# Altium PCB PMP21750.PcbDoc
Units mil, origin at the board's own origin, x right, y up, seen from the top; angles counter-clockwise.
Board outline 1000 x 600 mil, 2 copper layers (Top Layer, Bottom Layer), stack 62 mil thick; 15 components, 8 nets, 31 pads, 0 vias.
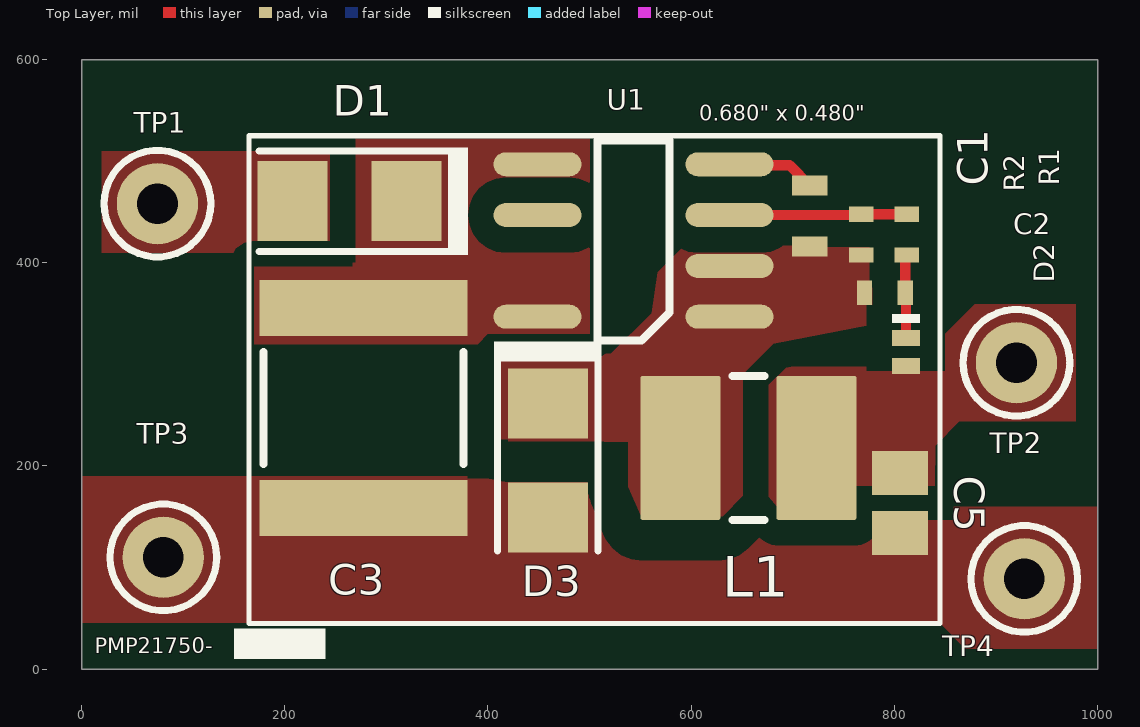
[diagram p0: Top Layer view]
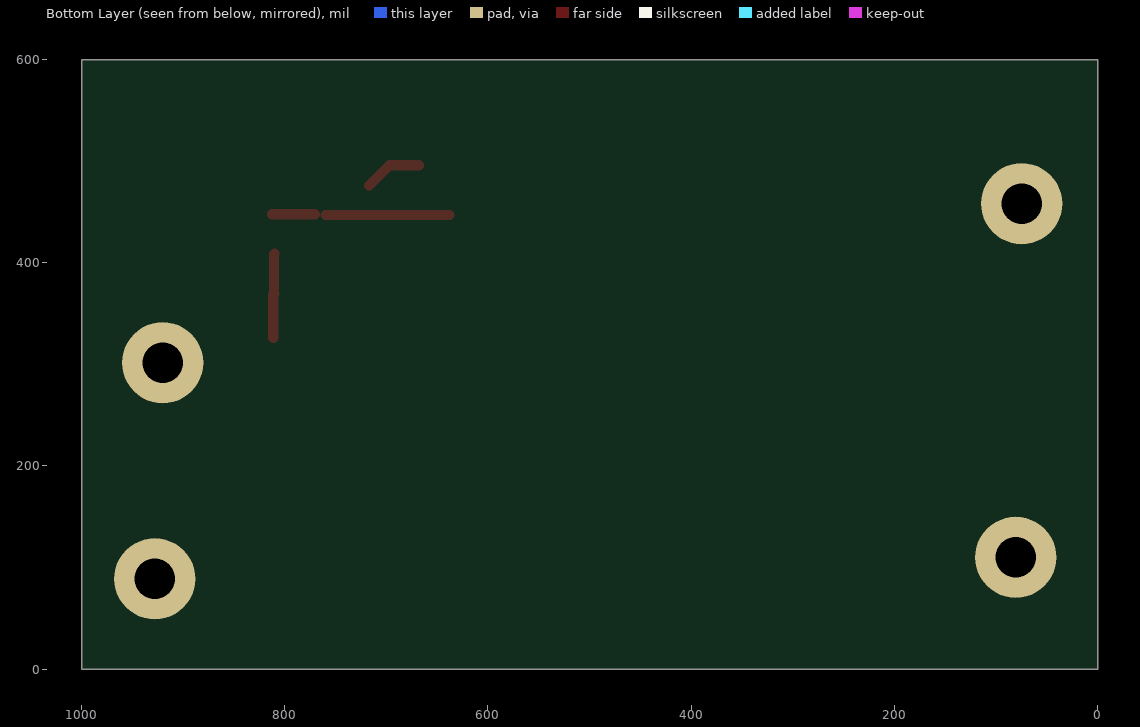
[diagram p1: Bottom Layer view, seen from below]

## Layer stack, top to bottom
Top Solder: solder mask 0.4, Solder Resist, Dk 3.5
Top Layer: signal copper 1.4
Dielectric1: core 59.2, FR-4, Dk 4.8
Bottom Layer: signal copper 1.4
Bottom Solder: solder mask 0.4, Solder Resist, Dk 3.5

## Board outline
0,0 0,600 1000,600 1000,0

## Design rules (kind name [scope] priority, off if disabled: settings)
AcuteAngle [All] p1: minimum=4.50000000000000E+0001 checktracksonly=FALSE
AssemblyTestPointUsage [All] p1: valid=2
Clearance Clearance_1 [InNetClass('HV') vs InNet('GND')] p1: gap=40 ignorepadtopadclearanceinfootprint=FALSE
Clearance Clearance_BoardEdge_MountingHoles [OnCopper and InComponentClass('Mounting Holes') vs IsKeepOut] p2: gap=40 ignorepadtopadclearanceinfootprint=FALSE except(0: Arc-Hole Track-Hole SMDPad-Hole THPad-Hole Via-Hole Fill-Hole Poly-Hole Region-Hole Text-Hole)
Clearance Clearance_BoardEdge_Poly [OnCopper and InPoly vs IsKeepOut] p3: gap=25 ignorepadtopadclearanceinfootprint=FALSE except(0: Arc-Hole Track-Hole SMDPad-Hole THPad-Hole Via-Hole Fill-Hole Poly-Hole Region-Hole Text-Hole)
Clearance Clearance_BoardEdge [OnCopper and Not InComponentClass('Logo') and not InComponentClass('FiducialMark') and not InRegion(1000,500,4000,800) and Not IsKeepout vs IsKeepOut] p4: gap=75 ignorepadtopadclearanceinfootprint=FALSE except(0: Arc-Hole Track-Hole SMDPad-Hole THPad-Hole Via-Hole Fill-Hole Poly-Hole Region-Hole Text-Hole)
Clearance Clearance_Poly [InPolygon] p5: gap=25 ignorepadtopadclearanceinfootprint=FALSE except(0: Arc-Hole Track-Hole SMDPad-Hole THPad-Hole Via-Hole Fill-Hole Poly-Hole Region-Hole Text-Hole)
Clearance [All] p6: gap=8 ignorepadtopadclearanceinfootprint=FALSE except(0: Arc-Hole Track-Hole SMDPad-Hole THPad-Hole Via-Hole Fill-Hole Poly-Hole Region-Hole Text-Hole)
ComponentClearance ComponentClearance_ScrewToNut [(HasFootprint('NY PMS 440 0025 PH')) vs (HasFootprint('Keystone_1902C'))] p1: gap=5 collisioncheckmode=3 verticalgap=10 showdistances=FALSE
ComponentClearance ComponentClearance_MountingHoles [InComponentClass('Mounting Holes')] p2: gap=2 collisioncheckmode=3 verticalgap=100000 showdistances=FALSE
ComponentClearance ComponentClearance_SmallPassives [HasFootprint('0201*') or HasFootprint('0402*') or HasFootprint('0508') or HasFootprint('0603*') or HasFootprint('0612') or HasFootprint('0805*') or HasFootprint('0815*') or HasFootprint('0830*') or HasFootprint('1206*') or HasFootprint('1210*') or HasFootprint('1808*') or HasFootprint('1812*') or HasFootprint('1825*') or HasFootprint('2010*') or HasFootprint('2220*') or HasFootprint('2225*') or HasFootprint('2512*') or HasFootprint('2728*') or HasFootprint('3518*') vs HasFootprint('0201*') or HasFootprint('0402*') or HasFootprint('0508') or HasFootprint('0603*') or HasFootprint('0612') or HasFootprint('0805*') or HasFootprint('0815*') or HasFootprint('0830*') or HasFootprint('1206*') or HasFootprint('1210*') or HasFootprint('1808*') or HasFootprint('1812*') or HasFootprint('1825*') or HasFootprint('2010*') or HasFootprint('2220*') or HasFootprint('2225*') or HasFootprint('2512*') or HasFootprint('2728*') or HasFootprint('3518*')] p3: gap=20 collisioncheckmode=3 verticalgap=10 showdistances=FALSE
ComponentClearance ComponentClearance_THtoSMT [IsThruComponent vs IsSMTComponent] p4: gap=20 collisioncheckmode=3 verticalgap=10 showdistances=FALSE
ComponentClearance ComponentClearance_THtoTH [IsThruComponent vs IsThruComponent] p5: gap=20 collisioncheckmode=3 verticalgap=20 showdistances=FALSE
ComponentClearance [All] p6: gap=10 collisioncheckmode=3 verticalgap=10 showdistances=FALSE
DiffPairsRouting [All] p1: maxlimit=100 minlimit=10 mostfreqgap=10 toplayer_minwidth=15 toplayer_maxwidth=15 toplayer_prefwidth=15 bottomlayer_minwidth=15 bottomlayer_maxwidth=15 bottomlayer_prefwidth=15 maxuncoupledlength=1000
FabricationTestPointUsage TestPointUsage [All] p1: valid=2 allowmultiple=FALSE
FabricationTestpoint Testpoint [All] p1: side=3 testpointundercomponent=TRUE minsize=40 maxsize=100 preferedsize=60 minholesize=0 maxholesize=40 preferedholesize=32 testpointgrid=1 allowsidetop=TRUE allowsidebottom=TRUE usegrid=TRUE gridtolerance=0.01
FanoutControl Fanout_LCC [IsLCC] p1: bgadir=Out bgaviamode=Centered fanoutstyle=Auto fanoutdirection=Alternating viagrid=1 // Fanout_LCC (Default Rule)
FanoutControl Fanout_BGA [IsBGA] p2: bgadir=Out bgaviamode=Centered fanoutstyle=Auto fanoutdirection=Alternating viagrid=1 // Fanout_BGA (Default Rule)
FanoutControl Fanout_Default [All] p4: bgadir=Out bgaviamode=Centered fanoutstyle=Auto fanoutdirection=Alternating viagrid=1 // Fanout_Default (Default Rule)
FanoutControl Fanout_Small [(CompPinCount < 5)] p5: bgadir=Out bgaviamode=Centered fanoutstyle=Auto fanoutdirection=OutThenIn viagrid=1 // Fanout_Small (Default Rule)
HoleSize [All] p1: absolutevalues=TRUE maxlimit=251 minlimit=8 maxpercent=80.000 minpercent=20.000
MinimumAnnularRing [All] p1: minimumring=9
MinimumSolderMaskSliver MinimumSolderMaskSliver_Logo [InComponentClass('Logo') vs InComponentClass('Logo')] p1: minsoldermaskwidth=0.7
MinimumSolderMaskSliver [All] p2: minsoldermaskwidth=4
PlaneConnect [All] p1: planeconnectstyle=Relief reliefexpansion=10 reliefentries=4 reliefconductorwidth=10 reliefairgap=10
PolygonConnect [All] p1: connectstyle=Direct reliefconductorwidth=20 reliefentries=4 polygonreliefangle="90 Angle" airgapwidth=10
RoutingVias [All] p1: holewidth=16 width=34 viastyle="Through Hole" minholewidth=8 minwidth=26 maxholewidth=40 maxwidth=65
SMDToCorner [All] p1: distance=30000
SilkToSilkClearance [All] p1: silktosilkclearance=5
SilkToSolderMaskClearance SilkscreenOverComponentPads [IsPad] p1: minsilkscreentomaskgap=5 clearancetoexposedcopper=TRUE
SolderMaskExpansion [All] p1: expansion=3
Width [All] p1: maxlimit=100 minlimit=6 preferedwidth=10 checkconnectedcopper=TRUE
16 further rules are at their usual default settings.

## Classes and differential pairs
net class HV: NetC1_2 NetC3_1

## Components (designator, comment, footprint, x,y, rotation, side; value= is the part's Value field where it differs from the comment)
C1 "C0603C104K8RACTU" 0603S 716.79,446.02 r270 top value=0.1uF
C2 "GRM155R71A224KE01D" 0402S 790.67,370.48 r180 top value=0.22uF
C3 "Capacitor" 2220_280L 277.63,257.08 r270 top value=2.2uF
C5 "GRM21BR60J107M" 0805L 805.8,163.45 r270 top value=100uF
D1 "CD1408-FU1600" Diode_1408 263.49,460.67 r180 top value=600V
D2 "BAS16L,315" SOD882 811.33,312.12 r270 top value=100V
D3 "CD1408-FU1600" Diode_1408 458.94,205.58 r270 top value=600V
L1 "744045681" WE-LQ_1812 656.41,217.8 r0 top value=680uH
R1 "CRCW040243K2FKED" 0402S 812.26,427.76 r270 top value=43.2k
R2 "ERJ-2RKF1002X" 0402S 767.43,427.76 r90 top value=10.0k
TP1 "5000" Keystone5000 74.72,458.19 r90 top
TP2 "5000" Keystone5000 920.18,301.57 r90 top
TP3 "5001" Keystone5001 80.53,110.04 r90 top
TP4 "5001" Keystone5001 927.9,88.88 r90 top
U1 "UCC28880D" D0007A_N 543.36,421.92 r180 top

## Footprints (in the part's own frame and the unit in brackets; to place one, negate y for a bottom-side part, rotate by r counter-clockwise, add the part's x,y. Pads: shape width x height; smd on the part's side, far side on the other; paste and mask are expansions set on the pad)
0402S [mil] "Based on C0402S footprint from PADS legacy"
  rect 15x24 smd: 1(-20,0) 2(20,0)
  body extent -22,-12 22,12, height 24
0603S [mil]
  rect 20x35 smd: 1(-30,0) 2(30,0)
  body extent -34,-19 34,19, height 39
0805L [mm] "0805 from SM-752 data"
  rect 1.1x1.4 smd: 1(-0.75,0) 2(0.75,0)
  body extent -1.1,-0.72 1.1,0.72, height 1.45
2220_280L [mm] "Chip Capacitor, Body 5.7x5.0mm, IPC High Density"
  rect 1.4x5.2 smd: 1(-2.5,0) 2(2.5,0)
  silkscreen extent -1.4,-2.5 1.4,2.5, body extent -2.95,-2.6 2.95,2.65, height 2.8
D0007A_N [mm] "SOIC, 7-Leads, Body 4.9x3.9mm, Pitch 1.27mm, IPC Medium Density"
  oval 2.2x0.6 smd: 1(-2.4,1.905) 2(-2.4,0.635) 3(-2.4,-0.635) 4(-2.4,-1.905) 5(2.4,-1.905) 6(2.4,-0.635) 8(2.4,1.905)
  silkscreen extent -0.9,-2.5 0.9,2.5, body extent -3,-2.5 3,2.5, height 1.54
Diode_1408 [mm] "On Semi recommended land pattern for SOD-123"
  rect 1.75x2 smd: 1(-1.425,0) 2(1.425,0)
  silkscreen extent -2.97,-1.35 2.26,1.35, body extent -1.8,-1.05 1.8,1.05, height 1.35
Keystone5000 [mil] "For Keystone 500x miniature loop terminals"
  round 80 hole 40: 1(0,0)
  silkscreen extent -52,-52 52,52, body extent -49,-49 49,49, height 182
Keystone5001 [mil] "For Keystone 500x miniature loop terminals"
  round 80 hole 40: 1(0,0)
  silkscreen extent -52,-52 52,52, body extent -49,-49 49,49, height 182
SOD882 [mm] "NXP Semiconductor"
  rect 0.4x0.7 smd paste-0.05: 1(-0.35,0) 2(0.35,0)
  silkscreen extent -0.95,-0.35 -0.72,0.35, body extent -0.51,-0.31 0.51,0.31, height 0.51
WE-LQ_1812 [mm] "SMD, 2-Leads, Body 4.5x3.2mm"
  rrect5% 2x3.6 smd: 1(-1.7,0) 2(1.7,0)
  silkscreen extent -0.4,-1.8 0.4,1.8, body extent -2.25,-1.6 2.25,1.6, height 2.6

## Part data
C1: library part CMP-0006862-5, "CAP, CERM, 0.1 uF, 10 V, +/- 10%, X7R, 0603", Cap_Case=0603, Manufacturer=Kemet, Supplier Part Number 1=399-1095-1-ND, TempCo=X7R, Tolerance_%=10%, Value1=Unknown, Value2=10V, ValueDisplayed=0.1uF
C2: library part CMP-0006630-2, "CAP, CERM, 0.22 uF, 10 V, +/- 10%, X7R, 0402", Cap_Case=0402, Manufacturer=MuRata, Supplier Part Number 1=490-12706-1-ND, TempCo=X7R, Tolerance_%=10%, Value1=Unknown, Value2=10V, ValueDisplayed=0.22uF
C3: library part CMP-0009372-2, "CAP, CERM, 2.2 uF, 450 V, +/- 10%, X6S, 2220", Cap_Case=2220, Manufacturer=TDK, PartNumber=C5750X6S2W225K250KA, Supplier Part Number 1=445-7781-1-ND, TempCo=X6S, Tolerance_%=10%, Value1=Unknown, Value2=450V, ValueDisplayed=2.2uF
C5: library part CMP-0008280-2, "CAP, CERM, 100 uF, 6.3 V, +/- 20%, X5R, 0805", Cap_Case=0805, Manufacturer=MuRata, TempCo=X5R, Tolerance_%=20%, Value1=Unknown, Value2=6.3V, ValueDisplayed=100uF
D1 D3: library part CMP-0029015-1, "Diode, Ultrafast, 600 V, 1 A, 1408 Diode", Manufacturer=Bourns, Supplier Part Number 1=CD1408-FU1600CT-ND, Value1=1A, Value2=1.25V
D2: library part CMP-0076954-1, "Diode, Switching, 100 V, 0.215 A, SOD882", Manufacturer=Nexperia, Supplier Part Number 1=568-4859-1-ND, Value1=0.215A, Value2=1.25V
L1: library part CMP-0084743-1, "Inductor, Wirewound, Ferrite, 680 µH, 0.09 A, 16.8 ohm, SMD", Manufacturer="Wurth Elektronik", Value1="16.8 ohm", Value2=0.09A, ValueDisplayed=680µH
R1: library part CMP-0026379-2, "RES, 43.2 k, 1%, 0.063 W, AEC-Q200 Grade 0, 0402", Manufacturer=Vishay-Dale, Power_W=63mW, Supplier Part Number 1=541-43.2KLCT-ND, TempCo="100 ppm/C", Tolerance_%=1%, Value2=0.063W, Value_Code=43k2, ValueDisplayed=43.2k
R2: library part CMP-0026658-1, "RES, 10.0 k, 1%, 0.1 W, 0402", Manufacturer=Panasonic, Power_W=100mW, Supplier Part Number 1=P10.0KLCT-ND, TempCo="100 ppm/C", Tolerance_%=1%, Value2=0.1W, Value_Code=10k0, ValueDisplayed=10.0k
TP1 TP2: library part CMP-0055137-1, "Test Point, Miniature, Red, TH", Color=Red, Manufacturer=Keystone, Supplier Part Number 1=36-5000-ND
TP3 TP4: library part CMP-0055138-1, "Test Point, Miniature, Black, TH", Color=Black, Manufacturer=Keystone, Supplier Part Number 1=36-5001-ND
U1: "Low Quiescent Current Switcher IC for AC/DC Power Supplies, D0007A", Alternate Manufacturer=None, Manufacturer="Texas Instruments"

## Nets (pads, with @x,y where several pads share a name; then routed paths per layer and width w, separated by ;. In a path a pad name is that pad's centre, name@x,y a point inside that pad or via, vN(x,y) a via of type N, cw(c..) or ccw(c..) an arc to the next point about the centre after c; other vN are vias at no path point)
GND: C3.2 C5.2 D3.2 TP3.1 TP4.1
NetC1_1: C1.1 U1.4 | length 56.9
  Top Layer w10: U1.4@668.12,495.9 696.91,495.9 C1.1
NetC1_2: C1.2 C2.2 D3.1 L1.1 R2.1 U1.1 U1.2
NetC2_1: C2.1 D2.1 R1.2 | length 83
  Top Layer w10: C2.1@810.17,369.8 811.33,368.64 D2.1 ; R1.2@810.17,408.91 810.67,408.41 C2.1
NetC3_1: C3.1 D1.1 U1.5 U1.8
NetC5_1: C5.1 D2.2 L1.2 TP2.1
NetD1_2: D1.2 TP1.1
NetR1_1: R1.1 R2.2 U1.3 | length 164.1
  Top Layer w10: U1.3 759.91,446.92 R2.2@759.98,446.85 ; R2.2@770.36,447.81 770.41,447.76 R1.1
pads on no net: U1.6

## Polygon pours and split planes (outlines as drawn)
GND on Top Layer "GND_L01_P054" (solid, remove dead copper, pour order 54): 0,190 840,190 840,160 1000,160 1000,20 870,20 844.45,45.55 0,45.55
NetC5_1 on Top Layer "NETC5_1_L01_P050" (solid, remove dead copper, pour order 50): 670,297.88 670,159.61 840,159.61 840,220 864.02,244.02 978.68,244.02 978.68,359.34 879.34,359.34 817.88,297.88
NetC1_2 on Top Layer "NETC1_2_L01_P048" (solid, remove dead copper, pour order 48): 411.01,310.45 411.01,224.38 514.09,224.38 522.1,216.38 551.01,150.45 631.01,150.45 651.01,170.45 651.01,290.45 681.01,320.45 779,339.19 785.18,421.82 598.17,421.82 567.01,390.66 561.01,350.45 521.01,310.45
NetD1_2 on Top Layer "NETD1_2_L01_P046" (solid, remove dead copper, pour order 46): 250,510 20,510 20,410 250,410
NetC3_1 on Top Layer "NETC3_1_L01_P044" (solid, pour order 44): 500,522.24 270,522.24 270,400 170,400 170,320 390,320 400,330 500,330
no net on Top Layer "NONET_L01_P026" (solid, remove dead copper, pour order 26): 0,190
no net on Top Layer "NONET_L01_P022" (solid, remove dead copper, pour order 22): 223.59,518.64
no net on Top Layer "NONET_L01_P018" (solid, remove dead copper, pour order 18): 25.32,512.9
no net on Top Layer "NONET_L01_P016" (solid, remove dead copper, pour order 16): 1005.17,429.57
no net on Top Layer "NONET_L01_P012" (solid, remove dead copper, pour order 12): 615.1,-237.08
no net on Top Layer "NONET_L01_P010" (solid, remove dead copper, pour order 10): -382.73,4086.55
no net on Top Layer "NONET_L01_P002" (solid, remove dead copper, pour order 2): 348.19,388.74

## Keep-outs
Keep-Out Layer:
  text ".Layer_Name" at 397,-978.49 h60

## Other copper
Top Layer:
  text ".Layer_Name" at 397,-978.49 h60
Bottom Layer:
  text ".Layer_Name" at 397,-978.49 h60

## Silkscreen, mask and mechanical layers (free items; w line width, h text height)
Top Overlay:
  rectangle: 150,10 240,40
  lines w5: 165,45 165,525 845,525 845,45 165,45
  text "0.680\" x 0.480\"" at 607.97,539.69 h15
  text "PMP21750-" at 13.05,15.85 h15
  text ".Layer_Name" at 397,-978.49 h60
Bottom Overlay:
  text ".Layer_Name" at 397,-978.49 h60
Top Paste:
  text ".Layer_Name" at 397,-978.49 h60
Bottom Paste:
  text ".Layer_Name" at 397,-978.49 h60
Top Solder:
  text ".Layer_Name" at 397,-978.49 h60
  text ".Layer_Name" at 397,-978.49 h60
Bottom Solder:
  text ".Layer_Name" at 397,-978.49 h60
Drill Guide:
  text ".Layer_Name" at 397,-978.49 h60
M1 Board Outline:
  the board outline again, w10
  text ".Layer_Name" at 397,-978.49 h60
M2 Board Dimensions:
  rectangle: -180.5,-405.5 -55.5,-280.5
  rectangle: -55.5,-530.5 319.5,-405.5
  lines w7: -180.5,-405.5 819.5,-405.5 ; -55.5,-530.5 -55.5,-280.5 ; 69.5,-530.5 69.5,-280.5 ; 319.5,-530.5 319.5,-280.5 ; 569.5,-530.5 569.5,-280.5 ; -180.5,-530.5 819.5,-530.5 819.5,-280.5 -180.5,-280.5 -180.5,-530.5
  lines w10: -180.5,-595.5 -180.5,-575.5 ; -120.5,-605.5 -180.5,-585.5 ; -120.5,-565.5 -180.5,-585.5 ; 43.58,-585.5 -180.5,-585.5 ; 595.42,-585.5 819.5,-585.5 ; 759.5,-605.5 819.5,-585.5 ; 759.5,-565.5 819.5,-585.5 ; 819.5,-595.5 819.5,-575.5
  text "1000 (mil)" at 53.58,-621.49 h60
  text ".Layer_Name" at 397,-978.49 h60
M3 3D STEP Top:
  text ".Layer_Name" at 397,-978.49 h60
M4 3D STEP Bottom:
  text ".Layer_Name" at 397,-978.49 h60
M5 Assembly Top:
  lines w7: 4959,-9.5 6084,-9.5 ; 4959,113 6081.5,113 ; 5274,-129.5 5274,233 ; 5659,-129.5 4959,-129.5 ; 5659,233 4959,233 ; 4959,-129.5 6084,-129.5 6084,233 4959,233 ; 4959,-129.5 4959,233
  lines w10: -472,-1050.17 6128,-1050.17 ; -472,-846.83 6130,-846.83 ; -472,-643.5 -472,-1253.5 3533,-1253.5 6130,-1253.5 6130,-643.5 -471.5,-643.5 -471.5,-1253.5 1104,-1253.5 ; 1993,-1253.5 1993,-643.5 ; 3260,-846.83 3260,-643.5 ; 4100,-846.83 4100,-643.5 ; 4722,-1260 4722,-1057.17
  text "TABLE 1" at 5346.5,268 h40
  text "Variant" at 4984,158 h40
  text "Label text" at 5419,158 h40
  text "001" at 5051.5,38 h40
  text "ChangeMe!" at 5329,35.5 h40
  text "002" at 5051.5,-87 h40
  text "ChangeMe!" at 5324,-89.5 h40
  text "COMPONENTS MARKED 'DNP' SHOULD NOT BE POPULATED." at 973.5,-438.5 h60
  text "ASSEMBLY VARIANT:" at 973,-554 h60
  text ".VariantName" at 2009,-554 h60
  text "PCB VIEWED FROM TOP SIDE" at -408.5,-775.67 h60
  text "BOARD #:" at 2068,-775.67 h60
  text ".PRJ_Number" at 2613.5,-775.67 h60
  text "REV:" at 3458,-775.67 h60
  text ".PCB_Rev" at 3749.5,-775.67 h60
  text "SVN REV:" at 4296,-775.67 h60
  text ".VersionControl_RevNumber" at 4802,-775.67 h60
  text "IGNORE ->" at -408.5,-978.49 h60
  text "PLOT NAME =" at -408.5,-1184.34 h60
  text ".plot_File_Name" at 397,-1184.34 h60
  text "GENERATED    :" at 2070,-1184.34 h60
  text ".Print_Date" at 2939.5,-1184.34 h60
  text ".Print_Time" at 3668.5,-1184.34 h60
  text "TEXAS INSTRUMENTS" at 4933,-1184.34 h60
M6 Assembly Bottom:
  lines w10: -472.5,-847.33 6129.5,-847.33 ; -470.5,-1050.67 6129.5,-1050.67 ; 935.5,-1260.5 935.5,-1057.67 ; 1557.5,-847.33 1557.5,-644 ; 2397.5,-847.33 2397.5,-644 ; 3664.5,-1254 3664.5,-644 ; 4553.5,-1254 6129,-1254 6129,-644 -472.5,-644 -472.5,-1254 2124.5,-1254 6129.5,-1254 6129.5,-644
  text "COMPONENTS MARKED 'DNP' SHOULD NOT BE POPULATED." at 5922,-438 h60
  text ".VariantName" at 4878,-554 h60
  text "ASSEMBLY VARIANT:" at 5917,-554 h60
  text ".VersionControl_RevNumber" at 855.5,-776.17 h60
  text "SVN REV:" at 1361.5,-776.17 h60
  text ".PCB_Rev" at 1908,-776.17 h60
  text "REV:" at 2199.5,-776.17 h60
  text ".PRJ_Number" at 3044,-776.17 h60
  text "BOARD #:" at 3589.5,-776.17 h60
  text "PCB VIEWED FROM BOTTOM SIDE" at 6066,-776.17 h60
  text "IGNORE ->" at 2367.85,-978.49 h60
  text "TEXAS INSTRUMENTS" at 724.5,-1184.84 h60
  text ".Print_Time" at 1989,-1184.84 h60
  text ".Print_Date" at 2718,-1184.84 h60
  text "GENERATED    :" at 3587.5,-1184.84 h60
  text ".plot_File_Name" at 5260.5,-1184.84 h60
  text "PLOT NAME =" at 6066,-1184.84 h60
M9 Title Sheet:
  drawing of 57 lines, arcs and shapes, not listed
  text "1" at 559.84,7916.5 h70
  text "2" at 3055.5,7916.5 h70
  text "3" at 5544.84,7916.5 h70
  text "4" at 8051.51,7916.5 h70
  text "5" at 10550.5,7916.5 h70
  text "6" at 13055.5,7916.5 h70
  text "A" at -596.5,6773.5 h70
  text "A" at 14203.5,6773.5 h70
  text "B" at -596.5,4393.5 h70
  text "B" at 14203.5,4393.5 h70
  text "C" at -596.5,2018.5 h70
  text "C" at 14203.5,2018.5 h70
  text "PROJECT TITLE:" at 11163.5,157.5 h45
  text ".PRJ_Title" at 11213.5,24.17 h70
  text "DESIGNED FOR:" at 11163.5,-143.5 h45
  text ".PRJ_Customer" at 11213.5,-283.5 h70
  text "D" at -596.5,-351.5 h70
  text "D" at 14203.5,-351.5 h70
  text "FILE NAME:" at 11163.5,-443.5 h45
  text ".PCB_File_Name_No_Path" at 11213.5,-563.5 h70
  text "Texas Instruments (TI) and/or its licensors do not warrant the accuracy or completeness of this specification" at 6194,-725.34 h45
  text "ENGINEER:" at 11163.5,-733.5 h45
  text "LAYOUT BY:" at 12668.5,-733.5 h45
  text "or any information contained therein. TI and/or its licensors do not warrant that this design will meet" at 6149.01,-838 h45
  text ".PRJ_Engineer" at 11213.5,-888.49 h70
  text ".PCB_Layout" at 12719,-888.49 h70
  text "the specifications, will be suitable for your application or fit for any particular purpose, or will operate in" at 6149.01,-950.67 h45
  text ".Layer_Name" at 397,-978.49 h60
  text "ALTIUM DESIGNER VERSION:" at 12668.5,-1043.5 h45
  text "an implementation. TI and/or its licensors do not warrant that the design is production worthy. You should" at 6149.01,-1063.33 h45
  text "completely validate and test your design implementation to confirm the system functionality for your application." at 6194,-1176 h45
  text ".print_Scale" at 11213.5,-1176.83 h70
  text ".Application_BuildNumber" at 12719,-1176.83 h70
  text "1" at 559.84,-1383.5 h70
  text "2" at 3055.5,-1383.5 h70
  text "3" at 5544.84,-1383.5 h70
  text "4" at 8051.51,-1383.5 h70
  text "5" at 10550.5,-1383.5 h70
  text "6" at 13055.5,-1383.5 h70
M10 Fab Notes:
  drawing of 212 lines, arcs and shapes, not listed
  text "DESIGN INFORMATION" at 12201.02,6690 h60
  text "(REFER ALSO ARRAY/PANEL PROFILING INFORMATION)" at 11839.46,6528.29 h60
  text "BOARD SIZE" at 11153.46,6524 h60
  text "1500MIL" at 11615.78,6396.18 h60
  text "X" at 12121.46,6396.18 h60
  text "2100MIL" at 12352.78,6396.18 h60
  text "Number of Layers :" at 11556.46,6199 h60
  text "1" at 12651.27,6189 h60
  text "MIN. TRACK WIDTH:" at 11556.46,6060 h60
  text "10" at 12652.7,6060 h60
  text "MIL" at 12807.46,6060 h60
  text "MIN. CLEARANCE:" at 11556.46,5928 h60
  text "10" at 12652.7,5928 h60
  text "MIL" at 12807.46,5928 h60
  text "MIN. VIA PAD SIZE:" at 11556.46,5796 h60
  text "10" at 12622.71,5796 h60
  text "MIL" at 12807.46,5796 h60
  text "0.05mm (2MIL)" at 12251.46,5654.29 h60
  text "MINIMUM ANNULAR RING" at 11227.23,5650 h60
  text "EXTERNAL" at 12959.46,5650 h60
  text "PER" at 11427.23,5532 h60
  text "IPC-D-275 CLASS 2 LEVEL C" at 11647.23,5532 h60
  text "MIL, HOLES" at 13135.46,5419.71 h60
  text "+/-" at 12743,5419 h60
  text "+/-" at 13597,5419 h60
  text "REGISTRATION TOLERANCES:" at 11227.23,5414 h60
  text "METAL" at 12427,5414 h60
  text "5" at 13003.2,5414 h60
  text "3" at 13836.2,5414 h60
  text "MIL" at 13952.46,5414 h60
  text "MATERIAL:" at 11152.46,5204.54 h60
  text "FR-4 High Tg" at 12138.9,5064.21 h60
  text "FR-408" at 11573.46,5055.64 h60
  text "X" at 11985.46,5055.64 h60
  text "OTHER" at 13061.46,5055.64 h60
  text "62 MIL (1.6mm) +/-10%" at 11893.56,4892.92 h60
  text "THICKNESS:" at 11227.23,4888.64 h60
  text "X" at 11765.4,4888.64 h60
  text "OTHER" at 13178.46,4888.64 h60
  text "TOLERANCE:" at 11227.23,4730.64 h60
  text "X" at 12066.53,4730.64 h60
  text "ANSI IPC-6012 TYPE 3 CLASS 2" at 12253.48,4730.64 h60
  text "OTHER +/-" at 12253.46,4574.64 h60
  text "BOW & TWIST:" at 11227.23,4417.64 h60
  text "X" at 12066.53,4417.64 h60
  text "ANSI IPC-6012 TYPE 3 CLASS 2" at 12253.48,4417.64 h60
  text "OTHER +/-" at 12253.46,4259.13 h60
  text "COPPER THICKNESS (FINISHED):" at 11152.46,4123.64 h60
  text "1.4MIL (1oz)" at 12032.46,3970.92 h60
  text "2MIL (1.4oz)" at 12799.46,3970.92 h60
  text "2.8MIL (2oz)" at 13526.46,3970.92 h60
  text "OUTER:" at 11509.46,3966.64 h60
  text "X" at 11904,3966 h60
  text "X" at 13400,3820 h60
  text "1.4MIL (1oz)" at 12032.46,3813.92 h60
  text "2.8MIL (2oz)" at 12799.46,3813.92 h60
  text "N/A" at 13526,3814.29 h60
  text "INNER SIGNAL:" at 11220.38,3809.64 h60
  text "DRILLING:" at 11152.46,3670.64 h60
  text "REFERENCE:" at 11227.23,3553.64 h60
  text "X" at 11875.46,3553.64 h60
  text "AS SHOWN" at 12062.46,3553.64 h60
  text "X" at 12776.46,3553.64 h60
  text "NC_DRILL FILES" at 12913.46,3553.64 h60
  text "PTH MIN COPPER THICKNESS:" at 11227.23,3395.64 h60
  text "X" at 12577.46,3395.64 h60
  text "1MIL" at 12714.46,3395.64 h60
  text "OTHER" at 13211.46,3395.64 h60
  text "BOARD FINISH:" at 11152.46,3236.64 h60
  text "SILKSCREEN:" at 11307.68,3118.64 h60
  text "X" at 12256.46,3118.64 h60
  text "TOP" at 12382.46,3118.64 h60
  text "BOTTOM" at 12893.46,3118.64 h60
  text "SILKSCREEN COLOR:" at 11307.68,2951.64 h60
  text "X" at 12255.42,2951.64 h60
  text "WHITE" at 12382.46,2951.64 h60
  text "OTHER" at 12893.46,2951.64 h60
  text "SOLDER RESIST COLOR:" at 11307.68,2781.64 h60
  text "X" at 11875.42,2622.44 h60
  text "GREEN" at 12002.46,2622.44 h60
  text "BLUE" at 12593.46,2622.44 h60
  text "OTHER" at 13131.46,2622.44 h60
  text "IMMERSION GOLD (ENIG)" at 12213.46,2433.92 h60
  text "ENEPIG" at 13551,2430.64 h60
  text "SURFACE FINISH:" at 11152.46,2429.64 h60
  text "IMM. TIN/SILVER OR EQUIV" at 11482,2272.64 h60
  text "OTHER" at 12913.46,2272.64 h60
  text "X" at 11310,2270 h60
  text "ARRAY/PANEL:" at 11152.46,2093.64 h60
  text "CUT AND TRIM PER MECH LAYER 1" at 12213.46,2089.35 h60
  text "N.C. ROUTE" at 12213.46,1937.64 h60
  text "X" at 12892.46,1937.64 h60
  text "V. SCORE" at 13079.46,1937.64 h60
  text "CERTIFICATION:" at 11152.46,1800.64 h60
  text "MATERIALS AND WORKMANSHIP FOR ALL PCBS" at 11877.46,1800.64 h60
  text "TO MEET OR EXCEED THE REQUIREMENTS OF:" at 11877.46,1702.64 h60
  text "X" at 11503.96,1566.13 h60
  text "ANSI IPC-A-600F CLASS ->" at 11642.96,1566.13 h60
  text "X" at 13282.02,1566.13 h60
  text "2" at 13400.96,1566.14 h60
  text "1" at 13085.96,1564.64 h60
  text "3" at 13754.96,1564.64 h60
  text "X" at 11506.02,1406.64 h60
  text "UL 94V-0" at 11642.96,1406.64 h60
  text "X" at 12318.02,1406.64 h60
  text "RoHS" at 12454.96,1406.64 h60
  text "OTHER" at 13099.36,1406.64 h60
  text "PER ORDER" at 13496.42,1406.64 h60
  text "ADDITIONAL REQUIREMENTS:" at 11152.46,1265.64 h60
  text "MICROSECTION:" at 11227.23,1150.64 h60
  text "YES" at 12132.96,1150.64 h60
  text "REQUIRED" at 12994.46,994.49 h60
  text "BARE BOARD ELEC. TEST:" at 11227.23,991.64 h60
  text "NONE" at 12532.96,991.64 h60
  text "PER ORDER" at 13586.46,991.64 h60
  text "X" at 12410,990 h60
  text "MANUFACTURER'S UL:" at 11227.23,834.64 h60
  text "RAIL" at 12392.96,830.35 h60
  text "METAL" at 12884.77,830.35 h60
  text "X" at 13260,830 h60
  text "SILK" at 13396.46,830.35 h60
  text ".Layer_Name" at 397,-978.49 h60
M11 Gerber Information:
  lines w10: -472,-1050.17 6128,-1050.17 ; -472,-846.83 6130,-846.83 ; -472,-643.5 -472,-1253.5 3533,-1253.5 6130,-1253.5 6130,-643.5 -471.5,-643.5 -471.5,-1253.5 1104,-1253.5 ; 1993,-1253.5 1993,-643.5 ; 3260,-846.83 3260,-643.5 ; 4100,-846.83 4100,-643.5 ; 4722,-1260 4722,-1057.17
  text "ALL ARTWORK VIEWED FROM TOP SIDE" at -408.5,-775.67 h60
  text "BOARD #:" at 2068,-775.67 h60
  text ".PRJ_Number" at 2613.5,-775.67 h60
  text "REV:" at 3458,-775.67 h60
  text ".PCB_Rev" at 3749.5,-775.67 h60
  text "SVN REV:" at 4296,-775.67 h60
  text ".VersionControl_RevNumber" at 4802,-775.67 h60
  text "LAYER NAME =" at -408.5,-978.49 h60
  text "PLOT NAME =" at -408.5,-1184.34 h60
  text ".plot_File_Name" at 397,-1184.34 h60
  text "GENERATED    :" at 2070,-1184.34 h60
  text ".Print_Date" at 2939.5,-1184.34 h60
  text ".Print_Time" at 3668.5,-1184.34 h60
  text "TEXAS INSTRUMENTS" at 4933,-1184.34 h60
M12 Stackup:
  lines w6: 11150,7396.33 13630,7396.33 ; 11150,7504.83 13630,7504.83 ; 11090,6895 ccw(c11125,6895) 11125,6860 13655,6860 ccw(c13655,6895) 13690,6895 13690,7625 ccw(c13655,7625) 13655,7660 11125,7660 ccw(c11125,7625) 11090,7625 11090,6895
  text "Layer Stack Up Detail for: PMP9073.PcbDoc" at 11150,7538.22 h59
  text "Layer" at 11150,7464.33 h25
  text "Gerber" at 12023.47,7464.33 h25
  text "Copper" at 12557.92,7464.33 h25
  text "Dielectric" at 13133.19,7464.33 h25
  text "Name" at 11150,7414.33 h25
  text "Document" at 12023.47,7414.33 h25
  text "Thickness" at 12557.92,7414.33 h25
  text "Material" at 13133.19,7414.33 h25
  text "Top Solder Mask" at 11150,7318.33 h35
  text "(.GTS)" at 12023.47,7318.33 h35
  text "Solder Resist" at 13133.19,7318.33 h35
  text "Top Layer" at 11150,7218.33 h35
  text "(.GTL)" at 12023.47,7218.33 h35
  text "1.4mil" at 12557.92,7218.33 h35
  text "FR-4" at 13133.19,7168.33 h35
  text "Bottom Layer" at 11150,7118.33 h35
  text "(.GBL)" at 12023.47,7118.33 h35
  text "1.4mil" at 12557.92,7118.33 h35
  text "Bottom Solder Mask" at 11150,7018.33 h35
  text "(.GBS)" at 12023.47,7018.33 h35
  text "Solder Resist" at 13133.19,7018.33 h35
  text ".Layer_Name" at 397,-978.49 h60
M13 Component Bodies Top:
  text ".Layer_Name" at 397,-978.49 h60
M14 Component Bodies Bottom:
  text ".Layer_Name" at 397,-978.49 h60
M15 Courtyards Top:
  text ".Layer_Name" at 397,-978.49 h60
M16 Courtyards Bottom:
  text ".Layer_Name" at 397,-978.49 h60
Drill Drawing:
  text ".Layer_Name" at 397,-978.49 h60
